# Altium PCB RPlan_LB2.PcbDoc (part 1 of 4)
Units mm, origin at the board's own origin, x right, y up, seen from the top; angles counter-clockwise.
Board outline 38.2 x 43.28 mm, 2 copper layers (Top Layer, Bottom Layer); 36 components, 100 nets, 269 pads, 31 vias.
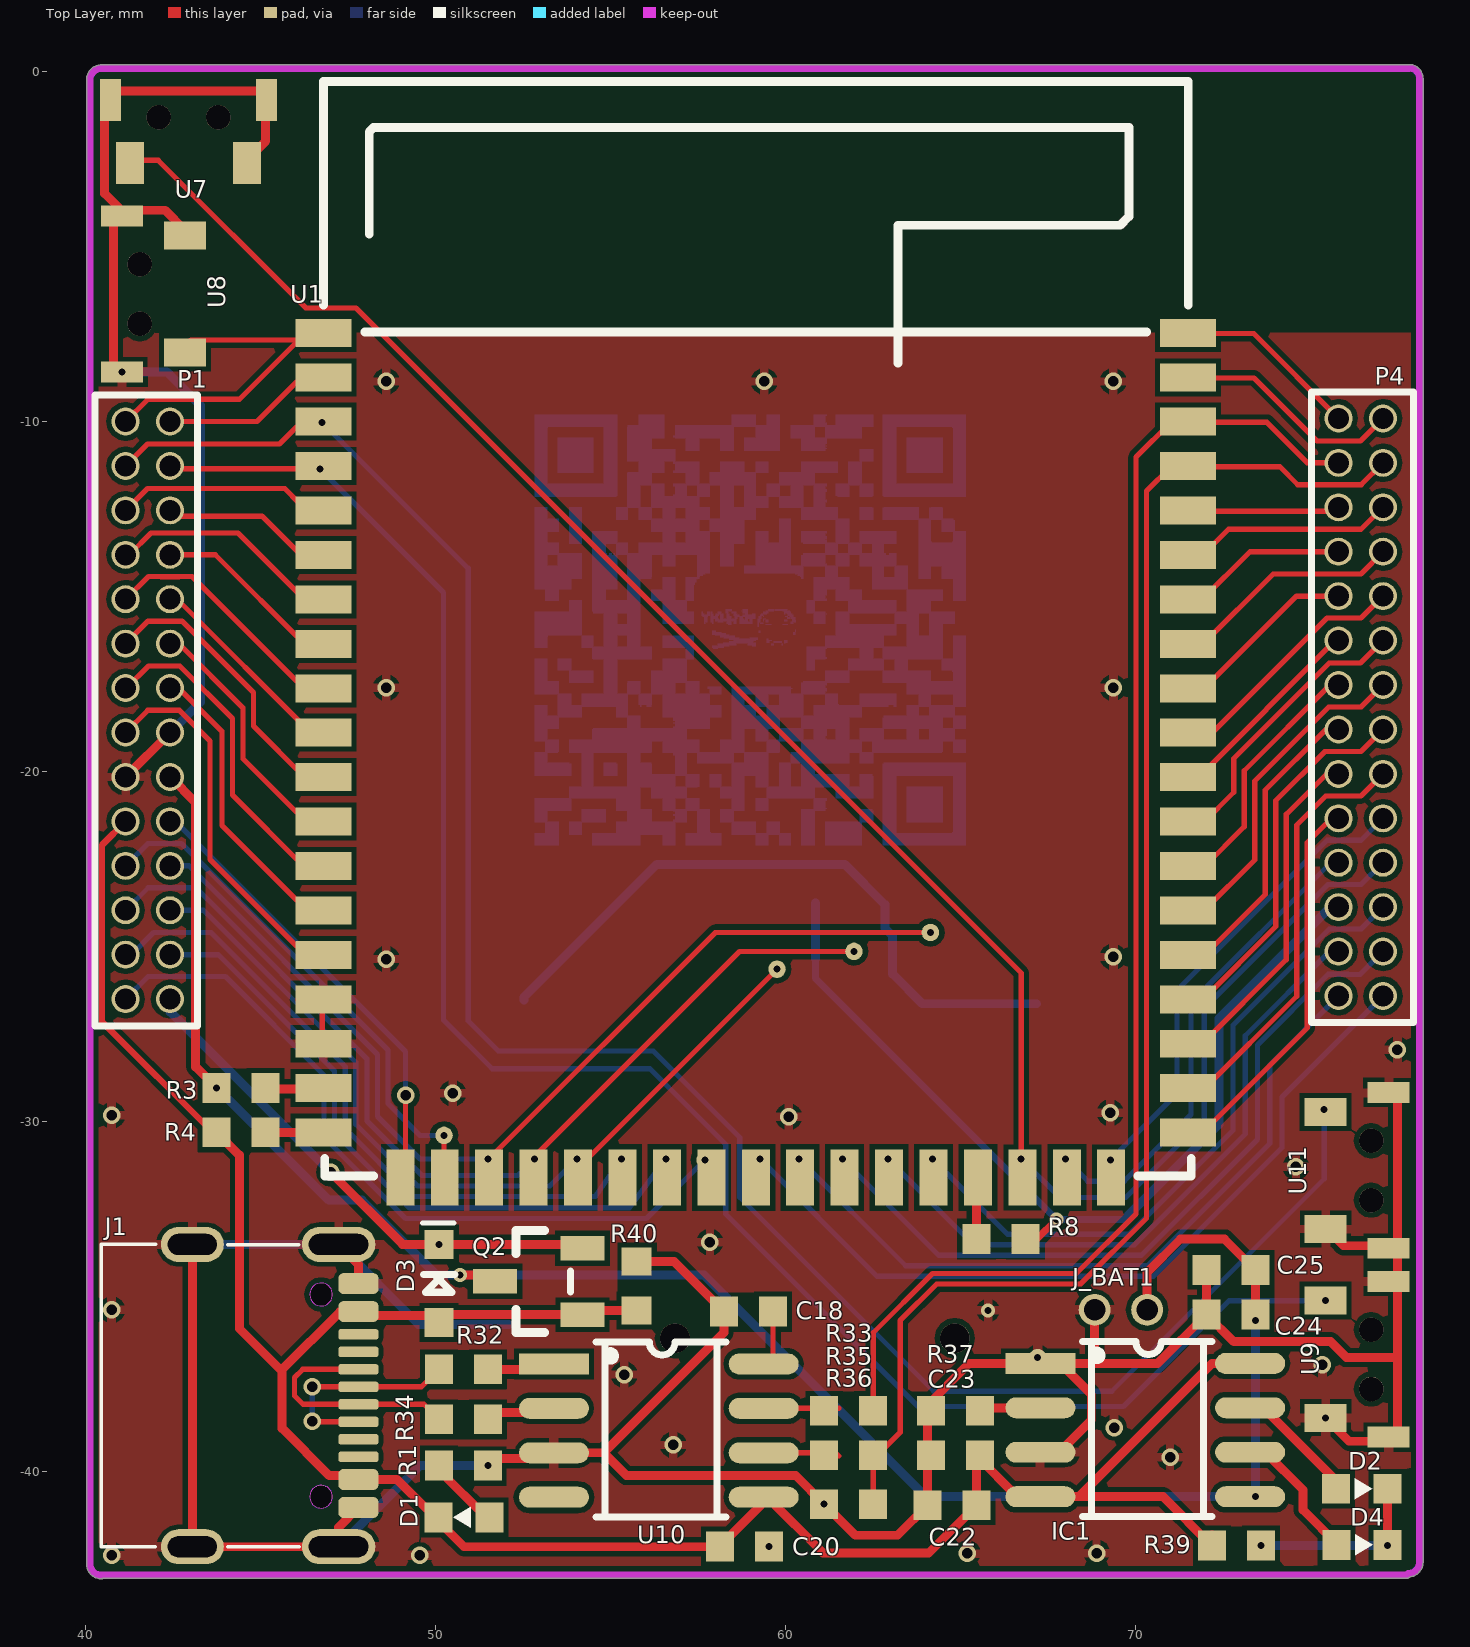
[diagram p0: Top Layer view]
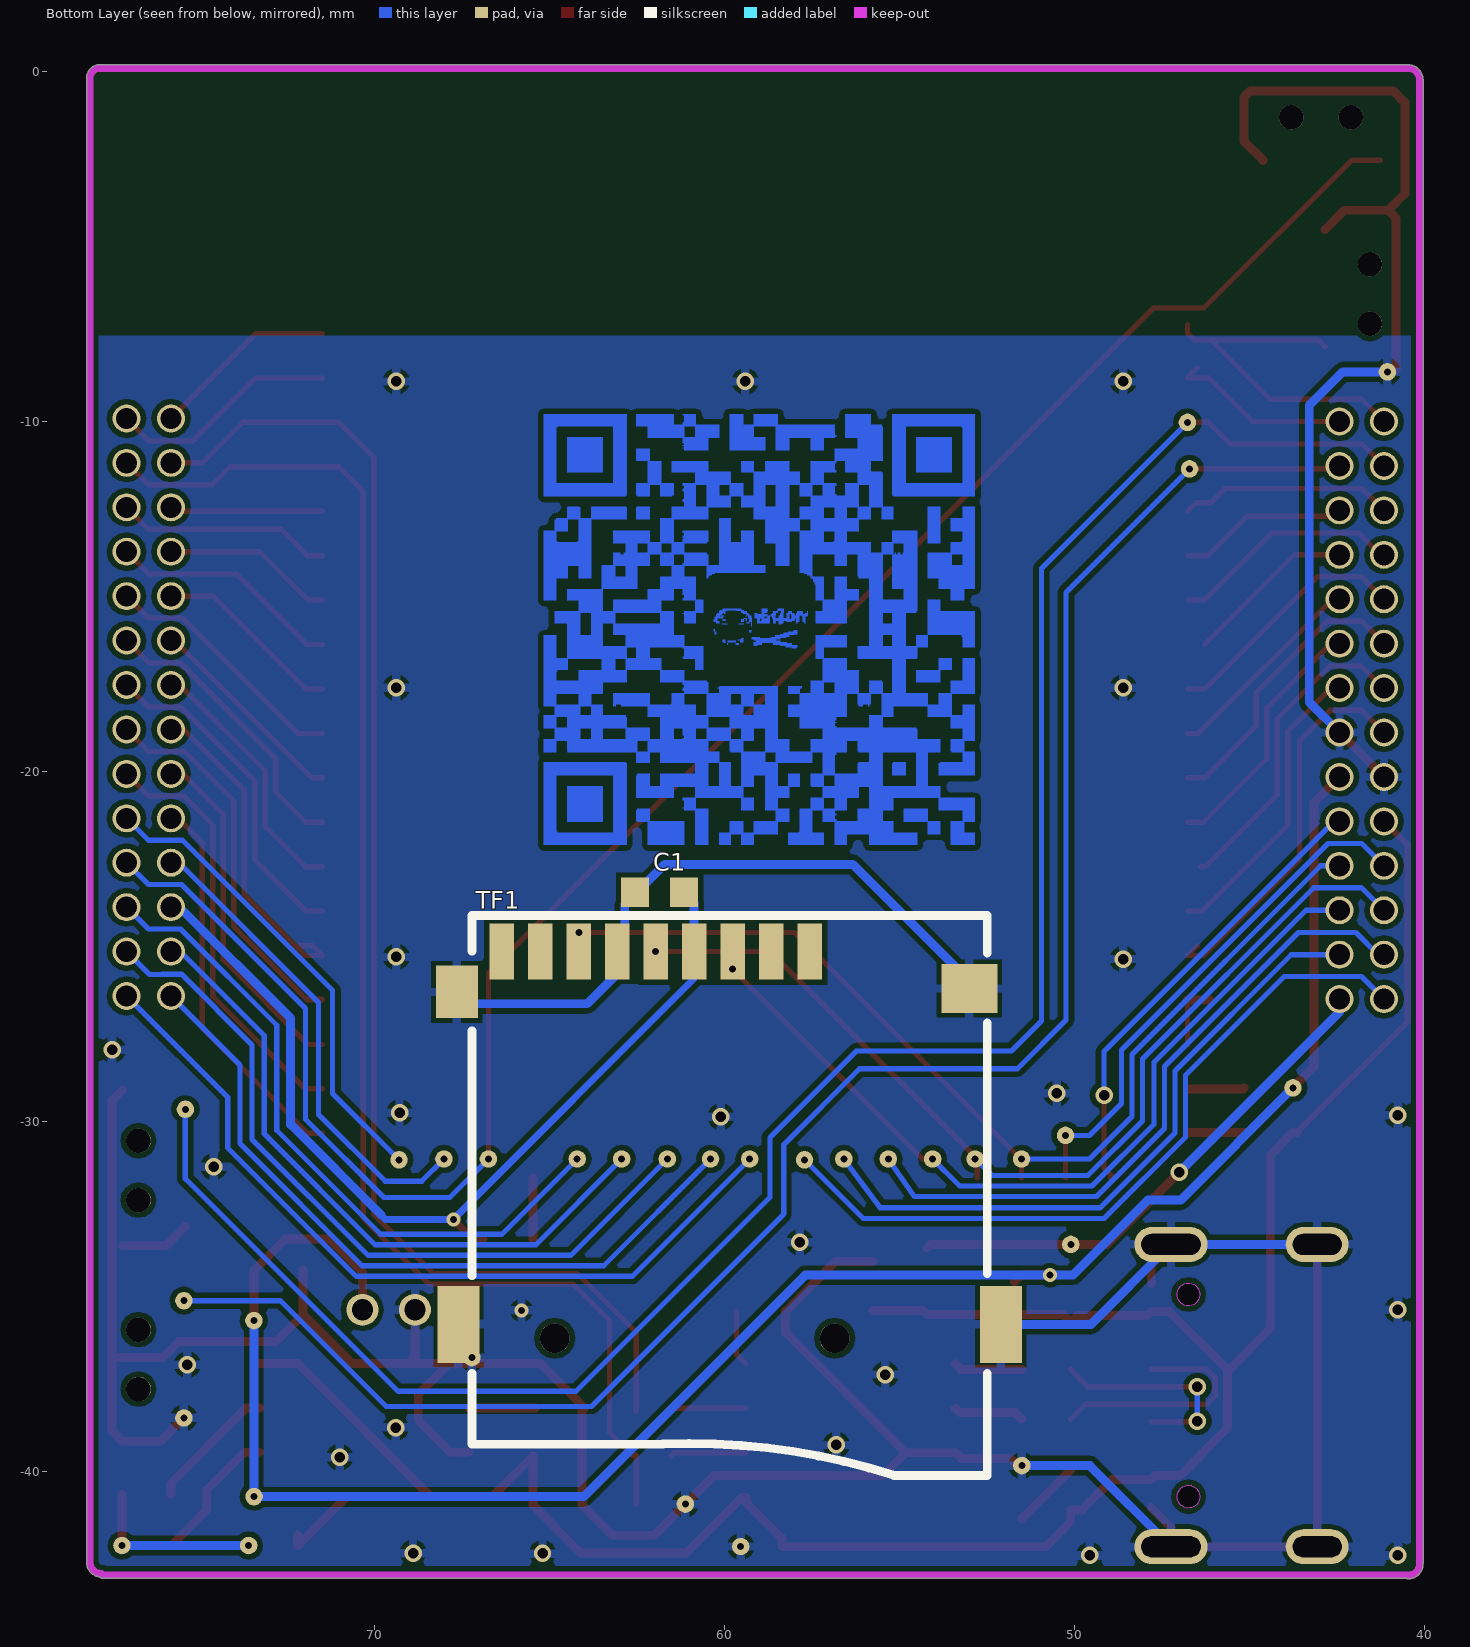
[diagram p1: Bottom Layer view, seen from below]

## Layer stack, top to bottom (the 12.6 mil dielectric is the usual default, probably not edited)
Top Solder: solder mask 0.0102, Solder Resist, Dk 3.5
Top Layer: signal copper 0.0356
Dielectric 1: dielectric 0.32, FR-4, Dk 4.8
Bottom Layer: signal copper 0.0356
Bottom Solder: solder mask 0.0102, Solder Resist, Dk 3.5

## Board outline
40.032,-42.65 cw(c40.132,-42.65) 40.035,-42.625 cw(c40.132,-42.6) 40.032,-42.6 40.032,-0.223 cw(c40.132,-0.223) 40.033,-0.207 cw(c40.456,-0.223) 40.456,0.2 77.802,0.2 cw(c77.841,0.108) 77.841,0.209 cw(c77.841,-0.183) 78.232,-0.183 78.232,-42.599 78.232,-42.6 ccw(c78.132,-42.6) 78.232,-42.599 78.232,-42.6 cw(c77.809,-42.6) 77.852,-43.021 cw(c77.773,-42.959) 77.773,-43.059 40.505,-43.059 cw(c40.455,-42.973) 40.455,-43.073 cw(c40.455,-42.65)

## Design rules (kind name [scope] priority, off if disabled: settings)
Clearance [All] p1: gap=0.15
PolygonConnect [All] p1: connectstyle=Relief reliefconductorwidth=0.254 reliefentries=4 polygonreliefangle="90 Angle" airgapwidth=0.127
RoutingVias [All] p1: holewidth=0.711 width=1.27 viastyle="Through Hole" minholewidth=0.711 minwidth=1.27 maxholewidth=0.711 maxwidth=1.27
SolderMaskExpansion [All] p1: expansion=0.102
Width [All] p1: maxlimit=0.254 minlimit=0.1 preferedwidth=0.254
30 further rules are at their usual default settings.

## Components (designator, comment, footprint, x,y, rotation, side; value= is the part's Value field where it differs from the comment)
C1 "0.1uf" 0603C 61.85,-23.45 r0 bottom
C18 "104" 0603C 58.955,-35.436 r180 top
C20 "104" 0603C 58.834,-42.15 r0 top
C22 "105" 0603C 64.77,-40.967 r0 top
C23 "104" 0603C 64.865,-39.542 r180 top
C24 "104" 0603C 72.744,-35.519 r180 top
C25 "106" 0603C 72.744,-34.249 r0 top
D1 "LED0" 0603_LED_R 50.85,-41.4 r0 top
D2 "LED0" 0603_LED_R 76.445,-40.421 r180 top
D3 "1N5819" SOD-323 50.1,-34.63 r90 top
D4 "LED0" 0603_LED_G 76.455,-42.1 r180 top
IC1 "TP4056/TC4056" SOP8_150mil 70.293,-38.821 r0 top
J1 "USB_TypeC" USB_TypeC 43.056,-42.156 r270 top
J_BAT1 "Header 2" BAT 69.596,-34.884 r180 top
P1 "connect" CONNECT2 43.325,-27.266 r180 top
P4 "connect" CONNECT2 74.912,-9.144 r0 top
Q2 "PMOS" SOT-23-3 52.959,-34.574 r0 top
R1 "10K" 0603C 50.8,-39.837 r180 top
R3 "" 0603C 44.45,-29.042 r180 top
R4 "" 0603C 44.45,-30.312 r180 top
R8 "" 0603C 66.167,-33.36 r0 top
R32 "0R" 0603C 50.8,-37.086 r180 top
R33 "1.2K" 0603C 61.817,-38.272 r180 top
R34 "0R" 0603C 50.8,-38.511 r180 top
R35 "1.2K" 0603C 61.817,-39.542 r180 top
R36 "1.5K" 0603C 61.817,-40.939 r0 top
R37 "1.5K" 0603C 64.865,-38.272 r180 top
R39 "4.7K" 0603C 72.898,-42.123 r180 top
R40 "100K" 0603C 55.753,-34.699 r270 top
TF1 "" TF1 57.567,-25.14 r180 bottom
U1 "RW052" RW052 59.16,-15.94 r0 top
U7 "key" KEY 42.947,-1.3 r0 top
U8 "key" KEY 41.55,-6.35 r90 top
U9 "key" KEY 76.75,-36.8 r270 top
U10 "CH330N" SOP8_150mil 56.388,-38.836 r0 top
U11 "key" KEY 76.75,-31.4 r270 top

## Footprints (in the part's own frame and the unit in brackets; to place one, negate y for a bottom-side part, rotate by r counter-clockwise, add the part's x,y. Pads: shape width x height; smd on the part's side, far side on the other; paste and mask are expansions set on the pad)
0603_LED_G [mm]
  rect 0.8x0.85 smd: 1(-0.765,0.007) 2(0.695,0.007)
  silkscreen extent -0.34,-0.29 0.17,0.31, body extent -0.84,-0.39 0.78,0.41, height 0.6
0603_LED_R [mm]
  rect 0.8x0.85 smd: 1(-0.765,0.08) 2(0.695,0.08)
  silkscreen extent -0.34,-0.22 0.17,0.38, body extent -0.84,-0.32 0.78,0.48, height 0.6
0603C [mm] "http://www.samsungsem.com/cn/front/downloadcms.do?path=%2F%2Fcn%2F%2Fsupport%2F%2Flibrary%2F%2Fproduct-catalog%2F%2F__icsFiles%2F%2Fafieldfile%2F%2F2015%2F%2F01%2F%2F12&fileName=CHIP_RESISTOR_150112_12.pdf"
  rect 0.8x0.85 smd: 1(-0.7,0) 2(0.7,0)
  Top Layer pour cut-out: -1.245,0.584 -1.245,-0.559 1.245,-0.559 1.245,0.584
  body extent -0.85,-0.45 0.85,0.45, height 0.55
BAT [mil]
  round 36 hole 24: 1(29.53,19.68) 2(-29.53,19.68)
CONNECT2 [mm]
  round 0.8 hole 0.6: 1(0.907,-0.762) 2(2.177,-0.762) 3(0.907,-2.032) 4(2.177,-2.032) 5(0.907,-3.302) 6(2.177,-3.302) 7(0.907,-4.572) 8(2.177,-4.572) 9(0.907,-5.842) 10(2.177,-5.842) 11(0.907,-7.112) 12(2.177,-7.112) 13(0.907,-8.382) 14(2.177,-8.382) 15(0.907,-9.652) 16(2.177,-9.652) 17(0.907,-10.922) 18(2.177,-10.922) 19(0.907,-12.192) 20(2.177,-12.192) 21(0.907,-13.462) 22(2.177,-13.462) 23(0.907,-14.732) 24(2.177,-14.732) 25(0.907,-16.002) 26(2.177,-16.002) 27(0.907,-17.272) 28(2.177,-17.272)
  silkscreen extent 0.13,-18.03 3.05,0, body extent 0.04,-18.11 3.14,0.07, height 3.4
KEY [mm]
  round 0.7 hole 0.7: 0(-0.85,0) 0(0.85,0)
  rect 0.8x1.2 smd: 1(1.675,-1.3) 2(-1.675,-1.3)
  rect 0.6x1.2 smd: 3(2.225,0.5) 4(-2.225,0.5)
  body extent -2.32,-2.2 2.33,2.1, height 2
RW052 [mm]
  rect 1.6x0.8 smd: 1(-12.36,8.48) 2(-12.36,7.21) 3(-12.36,5.94) 4(-12.36,4.67) 5(-12.36,3.4) 6(-12.36,2.13) 7(-12.36,0.86) 8(-12.36,-0.41) 9(-12.36,-1.68) 10(-12.36,-2.95) 11(-12.36,-4.22) 12(-12.36,-5.49) 13(-12.36,-6.76) 14(-12.36,-8.03) 15(-12.36,-9.3) 16(-12.36,-10.57) 17(-12.36,-11.84) 18(-12.36,-13.11) 19(-12.36,-14.38) 37(12.36,-14.38) 38(12.36,-13.11) 39(12.36,-11.84) 40(12.36,-10.57) 41(12.36,-9.3) 42(12.36,-8.03) 43(12.36,-6.76) 44(12.36,-5.49) 45(12.36,-4.22) 46(12.36,-2.95) 47(12.36,-1.68) 48(12.36,-0.41) 49(12.36,0.86) 50(12.36,2.13) 51(12.36,3.4) 52(12.36,4.67) 53(12.36,5.94) 54(12.36,7.21) 55(12.36,8.48)
  rect 0.8x1.6 smd: 20(-10.16,-15.66) 21(-8.89,-15.66) 22(-7.62,-15.66) 23(-6.35,-15.66) 24(-5.08,-15.66) 25(-3.81,-15.66) 26(-2.54,-15.66) 27(-1.27,-15.66) 28(0,-15.66) 29(1.27,-15.66) 30(2.54,-15.66) 31(3.81,-15.66) 32(5.08,-15.66) 33(6.35,-15.66) 34(7.62,-15.66) 35(8.89,-15.66) 36(10.16,-15.66)
  silkscreen extent -12.36,-15.62 12.45,15.66
SOD-323 [mm]
  rect 0.83x0.83 smd: 1(-1.115,0) 2(1.115,0)
  silkscreen extent -0.25,-0.46 1.73,0.46
SOP8_150mil [mm]
  rect 2x0.6 smd: 1(-2.997,1.905)
  rrect100% 2x0.6 smd: 2(-2.997,0.635) 3(-2.997,-0.635) 4(-2.997,-1.905) 5(2.997,-1.905) 6(2.997,-0.635) 7(2.997,0.635) 8(2.997,1.905)
  silkscreen extent -1.79,-2.47 1.91,2.53, body extent -3.05,-2.5 2.99,2.52, height 1.6
SOT-23-3 [mm]
  rect 1.25x0.7 smd: 1(1.25,-0.95) 2(1.25,0.95) 3(-1.25,0)
  silkscreen extent -0.65,-1.46 0.9,1.46, body extent -1.5,-1.5 1.5,1.5, height 1.3
TF1 [mm]
  rect 0.7x1.6 smd: 1(0,0) 2(-1.1,0) 3(-2.2,0) 4(-3.3,0) 5(-4.4,0) 6(-5.5,0) 7(-6.6,0) 8(-7.7,0) 9(-8.8,0)
  rect 1.2x1.5 smd: 10(-10.083,-1.16)
  rect 1.2x2.2 smd: 10(-10.033,-10.66) 10(5.467,-10.66)
  rect 1.6x1.4 smd: 10(4.567,-1.06)
  round 0.85 hole 0.85 unplated: NC(-7.283,-11.06) NC(0.717,-11.06)
  silkscreen extent -9.65,-14.98 5.08,1.02, body extent -10.42,-15.24 5.85,-0.05, height 2.3
USB_TypeC [mm]
  round 0.65 hole 0.65 unplated: 0(-7.21,3.68) 0(-1.43,3.68)
  rrect50% 0.6x1.15 smd: A1(-7.52,4.745) A4(-6.72,4.745) B1(-1.12,4.745) B4(-1.92,4.745)
  rrect50% 0.3x1.15 smd: A5(-5.57,4.745) A6(-4.57,4.745) A7(-4.07,4.745) A8(-3.07,4.745) B5(-2.57,4.745) B6(-3.57,4.745) B7(-5.07,4.745) B8(-6.07,4.745)
  oval 1x2.1 hole 0.6 slot 1.7 at 90 deg: GND(-8.64,4.18) GND(0,4.18)
  oval 1x1.8 hole 0.6 slot 1.4 at 90 deg: GND(-8.64,0) GND(0,0)
  Keep-Out Layer circle w0.025: c-1.43,3.68 r0.325
  Keep-Out Layer circle w0.025: c-7.21,3.68 r0.325
  silkscreen extent -8.64,-2.6 0,3.05, body extent -9.27,-3.78 0.63,6.22, height 3.3

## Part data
C1 C18 C20 C23 C24 C25: library part Cap, "Capacitor"
C22: library part CAP, "Capacitor"
D1 D2 D4: "Typical INFRARED GaAs LED"
D3: library part Diode_SOD123, "Diode"
IC1: library part 4056
J1: "USB"
J_BAT1: "Header, 2-Pin"
Q2: library part MOSFET_P_SOT23, "MOSFET"
R1 R32 R33 R34 R35 R36 R37 R39 R40: library part RES, "RES"
R3 R4 R8: library part Res2, "Resistor"
TF1: library part "HEADER 10"

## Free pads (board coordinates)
  round 0.5 hole 0.2: 39(50.25,-30.4) 40(51.507,-31.074) 41(52.832,-31.074) 42(54.048,-31.074) 43(55.317,-31.074) 44(56.587,-31.074) 45(57.71,-31.097) 46(59.277,-31.074) 47(60.397,-31.074) 48(61.633,-31.074) 49(62.937,-31.074) 50(64.207,-31.074) 52(66.747,-31.074) 53(68.017,-31.074) 55(73.598,-42.123) 56(77.22,-42.123) 80(64.15,-24.6) 81(61.967,-25.14) 82(59.767,-25.65) 83(75.408,-29.653) 84(75.45,-35.125) 85(46.767,-10.019) 86(46.704,-11.348) 87(69.3,-31.097) 90(50.1,-33.515) 92(73.45,-35.694) 93(73.444,-40.726) 95(43.75,-29.042) 111(59.534,-42.15) 112(61.117,-40.939) 113(51.5,-39.837) 114(75.45,-38.475) 115(41.05,-8.575) 116(67.219,-36.75)

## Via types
v1: diameter 0.5, hole 0.3, Top Layer to Bottom Layer, 28 vias
v2: diameter 0.4, hole 0.2, Top Layer to Bottom Layer, 3 vias

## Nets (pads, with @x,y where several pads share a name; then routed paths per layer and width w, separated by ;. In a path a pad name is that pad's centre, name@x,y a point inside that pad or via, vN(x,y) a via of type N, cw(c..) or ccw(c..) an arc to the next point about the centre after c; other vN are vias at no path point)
AGND: P4.14 U1.42 | length 9.6
  Top Layer w0.15: U1.42@71.487,-23.989 71.961,-23.989 73.424,-22.526 73.424,-20.267 75.539,-18.151 76.464,-18.151 P4.14@77.089,-17.526
AUDLN: P4.10 U1.46 | length 7.2
  Top Layer w0.15: U1.46@71.487,-18.909 72.191,-18.909 75.487,-15.613 76.462,-15.613 P4.10@77.089,-14.986
AUDLP: P4.9 U1.47 | length 5.4
  Top Layer w0.15: U1.47@71.487,-17.639 71.961,-17.639 74.614,-14.986 P4.9@75.819,-14.986
AUDRN: P4.12 U1.44 | length 8.3
  Top Layer w0.15: U1.44@71.487,-21.449 71.967,-21.449 72.824,-20.592 72.824,-19.626 75.55,-16.9 76.445,-16.9 P4.12@77.089,-16.256
AUDRP: P4.13 U1.43 | length 7.4
  Top Layer w0.15: U1.43@71.487,-22.719 71.979,-22.719 73.124,-21.575 73.124,-19.977 75.574,-17.526 P4.13@75.819,-17.526
CAM_PWND: 
CAM_RST: 
CEN: P4.22 pad.52 U1.34 U7.2 | length 57
  Top Layer w0.15: U7.2@41.251,-2.529 42.079,-2.529 46.3,-6.75 47.735,-6.75 66.747,-25.762 pad.52@66.747,-31.074
  Bottom Layer w0.15: pad.52@66.747,-31.074 67.851,-32.178 69.734,-32.178 71.976,-29.936 71.976,-26.774 75.519,-23.231 76.464,-23.231 P4.22@77.089,-22.606
GND: C1.2 C18.2 C20.2 C22.1 C23.2 C24.2 C25.1 IC1.1 IC1.3 J1.A1 J1.B1 J1.GND J_BAT1.1 P1.12 P1.13 pad.111 pad.112 pad.113 pad.114 pad.115 pad.116 R1.1 R36.1 R37.2 R40.1 TF1.6 TF1.10 U1.16 U1.17 U7.1 U7.3 U7.4 U8.1 U8.3 U8.4 U9.1 U9.3 U9.4 U10.3 U11.1 U11.3 U11.4 | length 144.6
  Top Layer w0.15: U1.17@46.767,-27.799 U1.16@46.767,-26.529
  Top Layer w0.254: pad.115@41.05,-8.575 41.018,-8.568 40.8,-8.518 40.8,-4.186 U8.3@41.029,-3.957 ; P1.12@41.148,-20.154 P1.13@42.418,-18.884 ; U8.1@42.829,-4.507 42.279,-3.957 U8.3@41.029,-3.957 ; J1.GND@43.056,-33.516 J1.GND@43.056,-42.156 J1.GND@47.236,-42.156 47.236,-41.601 J1.B1@47.801,-41.036 ; U7.1@44.601,-2.529 45.151,-1.979 45.151,-0.729 44.965,-0.543 40.887,-0.543 40.55,-0.88 40.55,-3.478 U8.3@41.029,-3.957 ; U1.16@46.128,-26.529 U1.16@46.767,-26.529 ; J1.GND@47.236,-33.516 47.801,-34.081 J1.A1@47.801,-34.636 ; pad.113@51.5,-39.964 51.825,-39.639 53.223,-39.639 U10.3@53.391,-39.471 54.815,-39.471 ; R40.1@55.753,-33.999 56.818,-33.999 C18.2@58.255,-35.436 58.255,-36.031 54.815,-39.471 ; IC1.3@67.296,-39.456 67.835,-39.456 68.75,-38.541 68.75,-37.802 IC1.1@67.864,-36.916 ; J_BAT1.1@68.846,-35.384 68.846,-36.732 69.03,-36.916 ; C25.1@72.044,-34.249 C24.2@72.044,-35.519 ; U11.1@75.408,-33.003 75.958,-33.553 U11.3@77.208,-33.553 ; pad.114@75.45,-38.475 76.116,-39.141 77.208,-39.141 77.5,-38.849 77.5,-36.75 ; U11.4@77.208,-29.103 77.5,-29.395 77.5,-36.75 ; 54.815,-39.471 55.462,-40.118 60.296,-40.118 pad.112@61.117,-40.939 62.006,-41.828 63.211,-41.828 64.07,-40.969 C22.1@64.07,-40.967 64.07,-38.251 64.005,-38.186 64.005,-38.176 65.265,-36.916 67.053,-36.916 pad.116@67.219,-36.75 67.31,-36.908 67.314,-36.916 IC1.1@67.864,-36.916 ; IC1.1@67.864,-36.916 69.03,-36.916 ; 69.03,-36.916 70.647,-36.916 C24.2@72.044,-35.519 ; C24.2@72.044,-35.519 72.821,-36.296 75.592,-36.296 76.047,-36.75 77.5,-36.75
  Bottom Layer w0.254: pad.115@41.05,-8.575 42.325,-8.575 43.283,-9.533 43.283,-18.019 P1.13@42.418,-18.884 ; J1.GND@43.056,-33.516 J1.GND@47.236,-33.516 49.52,-35.8 TF1.10@52.1,-35.8 ; J1.GND@47.236,-42.156 49.555,-39.837 pad.113@51.5,-39.837 ; TF1.10@52.531,-26.535 52.531,-26.453 56.333,-22.651 61.701,-22.651 62.85,-23.8 62.85,-24.478 63.067,-24.695 TF1.6@63.067,-25.14 63.067,-25.782 63.92,-26.635 TF1.10@67.181,-26.635
  other v1: 40.75,-42.4 49.555,-42.4 65.2,-42.35 68.9,-42.336 71,-39.6 56.8,-39.247 69.4,-38.75 55.4,-37.234 75.35,-36.95 40.75,-35.384 57.85,-33.45 74.6,-31.3 60.1,-29.862 40.75,-29.828 69.287,-29.75 50.5,-29.2 77.5,-27.95 48.6,-25.359 69.378,-25.3 48.6,-17.6 69.378,-17.6 48.6,-8.85 59.4,-8.85 69.378,-8.85
  other v2: 65.8,-35.399
IN_N: 
IN_P: 
LINEL: P4.5 U1.51 | length 4.4
  Top Layer w0.15: U1.51@71.487,-12.559 75.706,-12.559 P4.5@75.819,-12.446
MCLK: 
MIC_N: 
MIC_P: 
MICBIAS: P4.6 U1.50 | length 6.2
  Top Layer w0.15: U1.50@71.487,-13.829 71.921,-13.829 72.677,-13.073 76.462,-13.073 P4.6@77.089,-12.446
MICLN: P4.8 U1.48 | length 6.7
  Top Layer w0.15: U1.48@71.487,-16.369 71.931,-16.369 73.95,-14.35 76.455,-14.35 P4.8@77.089,-13.716
MICLP: P4.7 U1.49 | length 4.9
  Top Layer w0.15: U1.49@71.487,-15.099 71.901,-15.099 73.284,-13.716 P4.7@75.819,-13.716
MUTE: 
NetC2_1: 
NetC7_1: 
NetC8_1: 
NetC9_1: 
NetC15_2: 
NetC18_1: C18.1 U10.8 | length 1.6
  Top Layer w0.15: U10.8@59.385,-36.931 59.655,-36.661 C18.1@59.655,-35.436
NetD1_2: D1.2 R1.2 | length 2
  Top Layer w0.254: R1.2@50.1,-39.964 50.103,-39.964 D1.2@51.5,-41.361
NetD2_1: D2.1 D4.1 pad.55 pad.56 R39.1 | length 5.1
  Top Layer w0.254: pad.56@77.22,-42.123 D2.1@77.22,-40.655
  Bottom Layer w0.254: pad.55@73.598,-42.123 pad.56@77.22,-42.123
NetD2_2: D2.2 IC1.7 | length 3.7
  Top Layer w0.254: IC1.7@73.29,-38.186 73.665,-38.186 75.82,-40.341 D2.2@75.82,-40.655
NetD4_2: D4.2 IC1.6 | length 4
  Top Layer w0.254: IC1.6@73.29,-39.456 73.724,-39.456 74.803,-40.535 74.803,-41.106 D4.2@75.82,-42.123
NetIC1_2: IC1.2 R37.1 | length 1.9
  Top Layer w0.254: R37.1@65.405,-38.186 IC1.2@67.296,-38.186
NetQ1_1: 
NetQ1_3: 
NetR3_1: R3.1 U1.18 | length 1.6
  Top Layer w0.254: R3.1@45.15,-29.042 45.177,-29.069 U1.18@46.767,-29.069
NetR4_1: R4.1 U1.19 | length 1.6
  Top Layer w0.254: R4.1@45.15,-30.312 46.74,-30.312 U1.19@46.767,-30.339
NetR15_1: 
NetR16_1: 
NetR17_2: 
NetR18_2: 
NetR24_2: 
NetR26_2: 
NetR28_2: 
NetR32_1: R32.1 U10.1 | length 2
  Top Layer w0.254: R32.1@51.5,-37.086 53.236,-37.086 U10.1@53.391,-36.931
NetR33_2: R33.2 U10.7 | length 2.1
  Top Layer w0.15: U10.7@59.385,-38.201 61.53,-38.201
NetR34_1: R34.1 U10.2 | length 2
  Top Layer w0.254: R34.1@51.5,-38.511 51.689,-38.322 53.27,-38.322 U10.2@53.391,-38.201
NetR35_2: R35.2 U10.6 | length 2.2
  Top Layer w0.15: U10.6@59.385,-39.471 61.437,-39.471 61.53,-39.564
P0: P4.1 U1.55 | length 5.3
  Top Layer w0.15: U1.55@71.487,-7.479 73.392,-7.479 P4.1@75.819,-9.906
P1: P4.2 U1.54 | length 6.6
  Top Layer w0.15: U1.54@71.487,-8.749 73.399,-8.749 75.2,-10.55 76.445,-10.55 P4.2@77.089,-9.906
P2: P4.17 U1.39 | length 10
  Top Layer w0.15: U1.39@71.487,-27.799 71.901,-27.799 74.323,-25.377 74.323,-21.223 75.481,-20.066 P4.17@75.819,-20.066
P3: P4.19 U1.37 | length 11.2
  Top Layer w0.15: U1.37@71.487,-30.339 71.911,-30.339 74.923,-27.327 74.923,-22.026 75.614,-21.336 P4.19@75.819,-21.336
P4: P4.18 U1.38 | length 12.2
  Top Layer w0.15: U1.38@71.487,-29.069 71.976,-29.069 74.623,-26.421 74.623,-21.526 75.45,-20.7 76.455,-20.7 P4.18@77.089,-20.066
P5: P4.20 pad.87 U1.36 | length 13.6
  Bottom Layer w0.15: pad.87@69.3,-31.097 71.2,-29.197 71.2,-26.25 75.487,-21.963 76.462,-21.963 P4.20@77.089,-21.336
P6: P4.16 U1.40 | length 11.3
  Top Layer w0.15: U1.40@71.882,-26.502 71.514,-26.502 71.487,-26.529 71.924,-26.529 74.023,-24.429 74.023,-20.827 75.427,-19.423 76.462,-19.423 P4.16@77.089,-18.796
P7: P4.15 U1.41 | length 9.5
  Top Layer w0.15: U1.41@72.136,-24.978 71.768,-24.978 71.487,-25.259 71.98,-25.259 73.724,-23.515 73.724,-20.527 75.454,-18.796 P4.15@75.819,-18.796
P10: P4.4 R35.1 R36.2 U1.52 | length 42.2
  Top Layer w0.15: R36.2@62.517,-40.939 R35.1@62.517,-39.542 62.636,-39.542 63.287,-38.891 63.287,-35.694 64.332,-34.649 68.445,-34.649 70.326,-32.768 70.326,-11.983 71.02,-11.289 74.139,-11.289 74.651,-11.801 76.464,-11.801 P4.4@77.089,-11.176
P11: P4.3 R33.1 U1.53 | length 39.5
  Top Layer w0.15: R33.1@62.517,-38.272 62.517,-36.04 64.208,-34.349 68.321,-34.349 70.026,-32.644 70.026,-11.013 71.02,-10.019 73.769,-10.019 74.926,-11.176 P4.3@75.819,-11.176
P12: P1.26 pad.83 pad.85 U1.3 U11.2 | length 59.3
  Top Layer w0.15: P1.26@41.148,-11.264 41.777,-10.635 45.542,-10.635 46.158,-10.019 pad.85@46.767,-10.019
  Bottom Layer w0.15: pad.85@46.767,-10.019 50.94,-14.192 50.94,-27.126 51.799,-27.985 56.229,-27.985 58.7,-30.456 58.7,-32.167 64.246,-37.713 69.334,-37.713 75.408,-31.639 pad.83@75.408,-29.653
P13: P1.25 pad.84 pad.86 U1.4 U9.2 | length 53.7
  Top Layer w0.15: P1.25@42.418,-11.264 42.502,-11.348 pad.86@46.704,-11.348
  Bottom Layer w0.15: pad.86@46.704,-11.348 50.237,-14.881 50.237,-27.103 51.627,-28.493 56.139,-28.493 58.302,-30.656 58.302,-32.649 63.798,-38.145 69.668,-38.145 72.688,-35.125 pad.84@75.45,-35.125
P14: P1.6 pad.41 pad.81 TF1.5 U1.23 | length 28.9
  Top Layer w0.15: U1.23@52.777,-31.619 52.777,-31.056 58.693,-25.14 pad.81@61.967,-25.14 pad.81@61.851,-25.044
  Bottom Layer w0.15: P1.6@41.148,-23.964 41.793,-23.319 43.157,-23.319 48.05,-28.212 48.05,-29.983 49.616,-31.549 52.357,-31.549 pad.41@52.832,-31.074
P15: P1.4 pad.43 U1.25 | length 19.2
  Bottom Layer w0.15: P1.4@41.148,-25.234 41.316,-25.234 41.95,-24.6 43.59,-24.6 47.424,-28.434 47.424,-30.206 49.367,-32.149 54.563,-32.149 54.569,-32.143 pad.43@55.317,-31.074
P16: P1.5 pad.42 pad.82 TF1.3 U1.24 | length 24.2
  Top Layer w0.15: pad.42@54.048,-31.074 54.343,-31.074 pad.82@59.767,-25.65
  Bottom Layer w0.15: P1.5@42.418,-23.964 43.378,-23.964 47.724,-28.31 47.724,-30.081 49.492,-31.849 53.273,-31.849 pad.42@54.048,-31.074
P17: P1.7 pad.40 pad.80 TF1.7 U1.22 | length 29.5
  Top Layer w0.15: U1.22@51.507,-31.619 51.507,-31.097 58.004,-24.6 pad.80@64.15,-24.6
  Bottom Layer w0.15: P1.7@42.418,-22.694 42.956,-22.694 48.35,-28.088 48.35,-29.859 49.565,-31.074 pad.40@51.507,-31.074
P18: P1.3 pad.44 U1.26 | length 18.9
  Bottom Layer w0.15: P1.3@42.418,-25.234 43.799,-25.234 47.122,-28.556 47.122,-30.271 47.124,-30.274 47.124,-30.33 49.265,-32.471 55.543,-32.471 pad.44@56.587,-31.074
P19: P1.8 pad.39 U1.21 | length 14.9
  Top Layer w0.15: U1.21@50.237,-31.619 50.25,-31.606 pad.39@50.25,-30.4
  Bottom Layer w0.15: P1.8@41.148,-22.694 41.783,-22.059 42.746,-22.059 48.65,-27.963 48.65,-29.487 49.563,-30.4 pad.39@50.25,-30.4
P20: P4.24 pad.50 U1.32 | length 19.4
  Bottom Layer w0.15: pad.50@64.207,-31.074 66.358,-33.225 69.825,-33.225 72.798,-30.252 72.798,-27.252 75.55,-24.5 75.559,-24.5 75.56,-24.501 76.464,-24.501 P4.24@77.089,-23.876
P21: P4.25 pad.49 U1.31 | length 19
  Bottom Layer w0.15: pad.49@62.937,-31.074 65.388,-33.525 69.985,-33.525 73.15,-30.36 73.15,-27.55 75.554,-25.146 P4.25@75.819,-25.146
P22: P4.26 pad.48 U1.30 | length 21.8
  Bottom Layer w0.15: pad.48@61.633,-31.074 64.384,-33.825 70.187,-33.825 73.5,-30.512 73.5,-27.814 75.523,-25.791 76.078,-25.791 76.087,-25.8 76.435,-25.8 P4.26@77.089,-25.146
P23: P4.27 pad.47 U1.29 | length 21.2
  Bottom Layer w0.15: pad.47@60.397,-31.074 63.448,-34.125 70.355,-34.125 73.85,-30.63 73.85,-28.385 P4.27@75.819,-26.416
P24: P1.2 pad.45 U1.27 | length 21.4
  Bottom Layer w0.15: P1.2@41.148,-26.504 41.793,-25.859 44,-25.859 46.822,-28.68 46.822,-30.452 49.146,-32.776 56.032,-32.776 pad.45@57.71,-31.097
P25: P1.27 U1.2 | length 5.3
  Top Layer w0.15: P1.27@42.418,-9.994 44.9,-9.994 46.145,-8.749 46.767,-8.749 U1.2@46.486,-8.468
P26: P4.28 pad.46 U1.28 | length 23.4
  Bottom Layer w0.15: pad.46@59.277,-31.074 62.628,-34.425 70.528,-34.425 74.2,-30.753 74.2,-29.305 P4.28@77.089,-26.416
P27: P1.21 U1.8 | length 4.9
  Top Layer w0.15: P1.21@42.418,-13.804 43.711,-13.804 U1.8@46.276,-16.369
P28: P1.28 U1.1 U8.2 | length 10.3
  Top Layer w0.15: P1.28@41.148,-9.994 41.783,-9.359 44.402,-9.359 U1.1@46.096,-7.665 ; U8.2@42.829,-7.857 43.021,-7.665 U1.1@46.096,-7.665 ; U1.1@46.767,-7.229 46.767,-7.479 46.581,-7.665 U1.1@46.096,-7.665
P29: P1.22 U1.7 | length 6.7
  Top Layer w0.15: P1.22@41.148,-13.804 41.253,-13.804 41.878,-13.179 44.356,-13.179 46.276,-15.099 U1.7@46.767,-15.099
P30: P1.20 U1.9 | length 7.2
  Top Layer w0.15: P1.20@41.148,-15.074 41.8,-14.422 42.152,-14.422 42.159,-14.429 42.677,-14.429 42.684,-14.422 43.049,-14.422 46.266,-17.639 U1.9@46.767,-17.639
P31: P1.19 U1.10 | length 5.9
  Top Layer w0.15: P1.19@42.418,-15.074 42.624,-15.074 46.459,-18.909 U1.10@46.767,-18.909
P32: P1.23 U1.6 | length 4.9
  Top Layer w0.15: P1.23@42.418,-12.534 42.584,-12.7 45.046,-12.7 46.175,-13.829 U1.6@46.767,-13.829
P33: P1.24 U1.5 | length 6.1
  Top Layer w0.15: P1.24@41.148,-12.534 41.773,-11.909 45.696,-11.909 46.106,-12.319 46.527,-12.319 U1.5@46.767,-12.559
P34: P1.18 U1.11 | length 8.3
  Top Layer w0.15: P1.18@41.148,-16.344 41.792,-15.7 42.759,-15.7 44.8,-17.741 44.8,-18.696 46.283,-20.179 U1.11@46.767,-20.179
P35: P1.17 U1.12 | length 7.3
  Top Layer w0.15: P1.17@42.418,-16.344 42.666,-16.344 44.5,-18.178 44.5,-19.633 46.316,-21.449 U1.12@46.767,-21.449
P36: P1.16 U1.13 | length 9.2
  Top Layer w0.15: P1.16@41.148,-17.614 41.167,-17.614 41.8,-16.981 42.696,-16.981 44.2,-18.485 44.2,-20.67 46.249,-22.719 U1.13@46.382,-22.719
P37: P1.15 U1.14 | length 8.6
  Top Layer w0.15: P1.15@42.418,-17.614 42.664,-17.614 43.9,-18.85 43.9,-21.543 46.346,-23.989 U1.14@46.767,-23.989
P38: P1.14 U1.15 | length 11.2
  Top Layer w0.15: P1.14@41.148,-18.884 41.782,-18.25 42.687,-18.25 43.561,-19.124 43.561,-22.511 46.309,-25.259 46.767,-25.259 U1.15@46.486,-24.978
P39: P1.9 U1.20 | length 13.2
  Top Layer w0.15: U1.20@48.967,-31.619 48.914,-31.566 49.15,-31.329 v1(49.15,-29.25)
  Bottom Layer w0.15: P1.9@42.418,-21.424 42.574,-21.424 49.15,-28 v1(49.15,-29.25)
PCLK: 
SCL: 
SDA: 
SPK_VDD: 
USBN: J1.A7 J1.B7 R34.2 | length 6.8
  Top Layer w0.15: J1.B7@47.801,-37.086 46.212,-37.086 45.974,-37.324 45.974,-37.84 46.22,-38.086 J1.A7@47.801,-38.086 49.675,-38.086 R34.2@50.1,-38.511
USBP: J1.A6 J1.B6 R32.2 | length 6.1
  Top Layer w0.15: v1(46.482,-38.563) 46.505,-38.586 J1.B6@47.801,-38.586 ; v1(46.482,-37.586) J1.A6@47.801,-37.586 49.6,-37.586 R32.2@50.1,-37.086
  Bottom Layer w0.15: v1(46.482,-38.563) v1(46.482,-37.586)
V1.8: 
V2.8: 
VBAT: C24.1 C25.2 IC1.5 J_BAT1.2 P1.11 pad.92 pad.93 pad.95 Q2.3 R3.2 | length 56.3
  Top Layer w0.254: P1.11@42.418,-20.154 43.15,-20.886 43.15,-28.442 pad.95@43.75,-29.042 ; v2(50.7,-34.392) 51.527,-34.392 Q2.3@51.709,-34.574 ; J_BAT1.2@70.346,-35.384 70.346,-34.314 71.3,-33.36 72.555,-33.36 C25.2@73.444,-34.249 C24.1@73.444,-35.519
  Bottom Layer w0.254: pad.95@43.75,-29.042 46.958,-32.25 47.9,-32.25 50.042,-34.392 v2(50.7,-34.392) 57.686,-34.392 64.02,-40.726 pad.93@73.444,-40.726 73.444,-35.7 pad.92@73.45,-35.694
VCOM: P4.11 U1.45 | length 6
  Top Layer w0.15: U1.45@71.487,-20.179 71.796,-20.179 75.719,-16.256 P4.11@75.819,-16.256
VDD: C1.1 P4.23 R8.2 TF1.4 | length 26.6
  Top Layer w0.2: R8.2@66.867,-33.36 67.19,-33.36 v2(67.75,-32.8)
  Bottom Layer w0.2: TF1.4@60.867,-25.35 60.867,-25.917 v2(67.75,-32.8) 69.684,-32.8 69.817,-32.667
  Bottom Layer w0.254: TF1.4@60.867,-25.35 TF1.4@60.867,-25.14 C1.1@60.867,-23.754 ; 69.817,-32.667 72.4,-30.084 72.4,-27.052 75.576,-23.876 P4.23@75.819,-23.876
VDDRAM: R8.1 U1.33 | length 1.7
  Top Layer w0.254: R8.1@65.467,-33.36 65.467,-31.629 U1.33@65.477,-31.619
VIO: P4.21 pad.53 U1.35 | length 13.9
  Bottom Layer w0.15: pad.53@68.212,-31.074 pad.53@68.017,-31.074 68.65,-31.707 69.693,-31.707 71.6,-29.8 71.6,-26.6 75.594,-22.606 P4.21@75.819,-22.606
VO_N: 
VO_P: 
VPWR: D3.2 P1.1 pad.90 Q2.2 | length 15
  Top Layer w0.254: v1(47.005,-31.455) 49.065,-33.515 pad.90@50.1,-33.515 54.1,-33.515 Q2.2@54.209,-33.624
  Bottom Layer w0.254: P1.1@42.418,-26.504 42.418,-26.868 v1(47.005,-31.455)
VUSB: C20.1 C22.2 C23.1 D1.1 D3.1 IC1.4 IC1.8 J1.A4 J1.B4 P1.10 Q2.1 R4.2 R39.2 R40.2 U10.5 | length 70.3
  Top Layer w0.18: P1.10@41.148,-21.424 40.472,-22.1 40.472,-27.15 R4.2@43.634,-30.312
  Top Layer w0.254: R4.2@43.634,-30.312 R4.2@43.75,-30.312 44.4,-30.962 44.4,-35.918 45.562,-37.08 ; 45.599,-37.117 47.28,-35.436 J1.A4@47.801,-35.436 47.914,-35.549 49.904,-35.549 D3.1@50.1,-35.745 50.321,-35.524 Q2.1@54.209,-35.524 54.334,-35.399 R40.2@55.753,-35.399 ; 45.622,-37.178 45.622,-38.772 46.974,-40.124 47.689,-40.124 J1.B4@47.801,-40.236 48.914,-40.236 49.785,-41.107 50.1,-41.107 50.1,-41.436 50.82,-42.156 58.355,-42.156 58.355,-41.911 59.385,-40.88 U10.5@59.385,-40.741 59.491,-40.741 61.086,-42.336 64.101,-42.336 C22.2@65.47,-40.967 65.47,-39.564 66.632,-40.726 IC1.4@67.296,-40.726 68.393,-40.726 ; R39.2@72.198,-41.818 R39.2@72.198,-42.123 70.801,-40.726 68.393,-40.726 ; IC1.8@73.29,-36.916 72.203,-36.916 68.393,-40.726
pads on no net: J1.0 J1.A5 J1.A8 J1.B5 J1.B8 TF1.1 TF1.2 TF1.8 TF1.9 TF1.NC U7.0 U8.0 U9.0 U10.4 U11.0
copper on no net: | length 3160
